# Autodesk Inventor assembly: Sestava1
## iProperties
Shininess: 64.0
Length Units: 11269
Angle Units: 11279
Time Units: 11290
Mass Units: 11283
Length Display Precision: 3
Angle Display Precision: 2
Compacted: True
Created: 2003-07
Part Number: Sestava1
Document SubType Name: Assembly
Designer: rudolf_martonka
Density: 0.0
Volumn: 0.0
Area: 0.0
PropertySet Name: Model Information
Control State: 0
Master: False
Checked Out: False
Author: rudolf_martonka
